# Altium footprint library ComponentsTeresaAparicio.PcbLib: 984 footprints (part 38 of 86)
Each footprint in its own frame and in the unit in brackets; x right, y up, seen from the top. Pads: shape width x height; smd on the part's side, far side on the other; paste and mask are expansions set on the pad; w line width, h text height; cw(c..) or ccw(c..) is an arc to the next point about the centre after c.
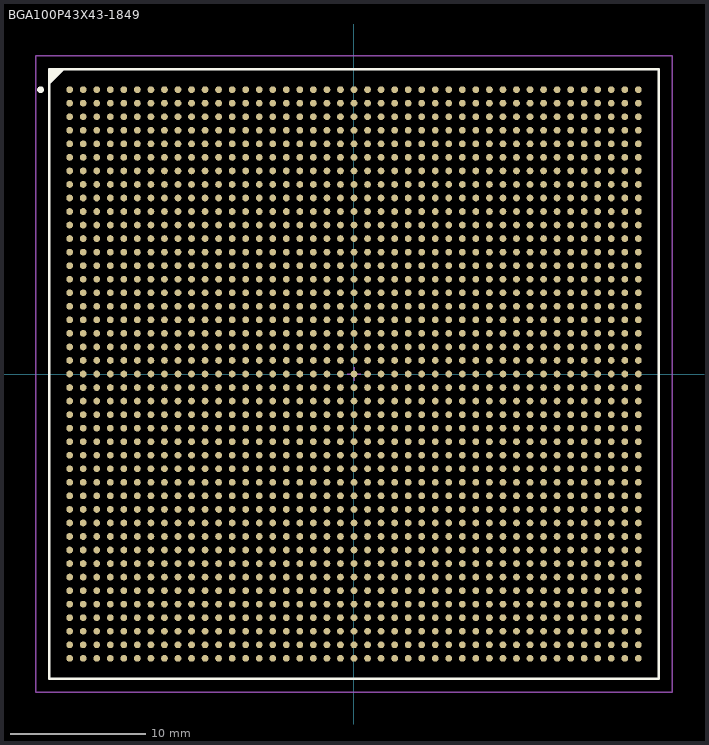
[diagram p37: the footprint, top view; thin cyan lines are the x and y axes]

## BGA100P43X43-1849 [mm] "BGA, 1849-Leads, Body 45x45mm, Pitch 1mm"
height 3.5
pads (1849):
  round 0.5 smd: A1(-21,21) A2(-20,21) A3(-19,21) A4(-18,21) A5(-17,21) A6(-16,21) A7(-15,21) A8(-14,21) A9(-13,21) A10(-12,21) A11(-11,21) A12(-10,21) A13(-9,21) A14(-8,21) A15(-7,21) A16(-6,21) A17(-5,21) A18(-4,21) A19(-3,21) A20(-2,21) A21(-1,21) A22(0,21) A23(1,21) A24(2,21) A25(3,21) A26(4,21) A27(5,21) A28(6,21) A29(7,21) A30(8,21) A31(9,21) A32(10,21) A33(11,21) A34(12,21) A35(13,21) A36(14,21) A37(15,21) A38(16,21) A39(17,21) A40(18,21) A41(19,21) A42(20,21) A43(21,21) AA1(-21,1) AA2(-20,1) AA3(-19,1) AA4(-18,1) AA5(-17,1) AA6(-16,1) AA7(-15,1) AA8(-14,1) AA9(-13,1) AA10(-12,1) AA11(-11,1) AA12(-10,1) AA13(-9,1) AA14(-8,1) AA15(-7,1) AA16(-6,1) AA17(-5,1) AA18(-4,1) AA19(-3,1) AA20(-2,1) AA21(-1,1) AA22(0,1) AA23(1,1) AA24(2,1) AA25(3,1) AA26(4,1) AA27(5,1) AA28(6,1) AA29(7,1) AA30(8,1) AA31(9,1) AA32(10,1) AA33(11,1) AA34(12,1) AA35(13,1) AA36(14,1) AA37(15,1) AA38(16,1) AA39(17,1) AA40(18,1) AA41(19,1) AA42(20,1) AA43(21,1) AB1(-21,0) AB2(-20,0) AB3(-19,0) AB4(-18,0) AB5(-17,0) AB6(-16,0) AB7(-15,0) AB8(-14,0) AB9(-13,0) AB10(-12,0) AB11(-11,0) AB12(-10,0) AB13(-9,0) AB14(-8,0) AB15(-7,0) AB16(-6,0) AB17(-5,0) AB18(-4,0) AB19(-3,0) AB20(-2,0) AB21(-1,0) AB22(0,0) AB23(1,0) AB24(2,0) AB25(3,0) AB26(4,0) AB27(5,0) AB28(6,0) AB29(7,0) AB30(8,0) AB31(9,0) AB32(10,0) AB33(11,0) AB34(12,0) AB35(13,0) AB36(14,0) AB37(15,0) AB38(16,0) AB39(17,0) AB40(18,0) AB41(19,0) AB42(20,0) AB43(21,0) AC1(-21,-1) AC2(-20,-1) AC3(-19,-1) AC4(-18,-1) AC5(-17,-1) AC6(-16,-1) AC7(-15,-1) AC8(-14,-1) AC9(-13,-1) AC10(-12,-1) AC11(-11,-1) AC12(-10,-1) AC13(-9,-1) AC14(-8,-1) AC15(-7,-1) AC16(-6,-1) AC17(-5,-1) AC18(-4,-1) AC19(-3,-1) AC20(-2,-1) AC21(-1,-1) AC22(0,-1) AC23(1,-1) AC24(2,-1) AC25(3,-1) AC26(4,-1) AC27(5,-1) AC28(6,-1) AC29(7,-1) AC30(8,-1) AC31(9,-1) AC32(10,-1) AC33(11,-1) AC34(12,-1) AC35(13,-1) AC36(14,-1) AC37(15,-1) AC38(16,-1) AC39(17,-1) AC40(18,-1) AC41(19,-1) AC42(20,-1) AC43(21,-1) AD1(-21,-2) AD2(-20,-2) AD3(-19,-2) AD4(-18,-2) AD5(-17,-2) AD6(-16,-2) AD7(-15,-2) AD8(-14,-2) AD9(-13,-2) AD10(-12,-2) AD11(-11,-2) AD12(-10,-2) AD13(-9,-2) AD14(-8,-2) AD15(-7,-2) AD16(-6,-2) AD17(-5,-2) AD18(-4,-2) AD19(-3,-2) AD20(-2,-2) AD21(-1,-2) AD22(0,-2) AD23(1,-2) AD24(2,-2) AD25(3,-2) AD26(4,-2) AD27(5,-2) AD28(6,-2) AD29(7,-2) AD30(8,-2) AD31(9,-2) AD32(10,-2) AD33(11,-2) AD34(12,-2) AD35(13,-2) AD36(14,-2) AD37(15,-2) AD38(16,-2) AD39(17,-2) AD40(18,-2) AD41(19,-2) AD42(20,-2) AD43(21,-2) AE1(-21,-3) AE2(-20,-3) AE3(-19,-3) AE4(-18,-3) AE5(-17,-3) AE6(-16,-3) AE7(-15,-3) AE8(-14,-3) AE9(-13,-3) AE10(-12,-3) AE11(-11,-3) AE12(-10,-3) AE13(-9,-3) AE14(-8,-3) AE15(-7,-3) AE16(-6,-3) AE17(-5,-3) AE18(-4,-3) AE19(-3,-3) AE20(-2,-3) AE21(-1,-3) AE22(0,-3) AE23(1,-3) AE24(2,-3) AE25(3,-3) AE26(4,-3) AE27(5,-3) AE28(6,-3) AE29(7,-3) AE30(8,-3) AE31(9,-3) AE32(10,-3) AE33(11,-3) AE34(12,-3) AE35(13,-3) AE36(14,-3) AE37(15,-3) AE38(16,-3) AE39(17,-3) AE40(18,-3) AE41(19,-3) AE42(20,-3) AE43(21,-3) AF1(-21,-4) AF2(-20,-4) AF3(-19,-4) AF4(-18,-4) AF5(-17,-4) AF6(-16,-4) AF7(-15,-4) AF8(-14,-4) AF9(-13,-4) AF10(-12,-4) AF11(-11,-4) AF12(-10,-4) AF13(-9,-4) AF14(-8,-4) AF15(-7,-4) AF16(-6,-4) AF17(-5,-4) AF18(-4,-4) AF19(-3,-4) AF20(-2,-4) AF21(-1,-4) AF22(0,-4) AF23(1,-4) AF24(2,-4) AF25(3,-4) AF26(4,-4) AF27(5,-4) AF28(6,-4) AF29(7,-4) AF30(8,-4) AF31(9,-4) AF32(10,-4) AF33(11,-4) AF34(12,-4) AF35(13,-4) AF36(14,-4) AF37(15,-4) AF38(16,-4) AF39(17,-4) AF40(18,-4) AF41(19,-4) AF42(20,-4) AF43(21,-4) AG1(-21,-5) AG2(-20,-5) AG3(-19,-5) AG4(-18,-5) AG5(-17,-5) AG6(-16,-5) AG7(-15,-5) AG8(-14,-5) AG9(-13,-5) AG10(-12,-5) AG11(-11,-5) AG12(-10,-5) AG13(-9,-5) AG14(-8,-5) AG15(-7,-5) AG16(-6,-5) AG17(-5,-5) AG18(-4,-5) AG19(-3,-5) AG20(-2,-5) AG21(-1,-5) AG22(0,-5) AG23(1,-5) AG24(2,-5) AG25(3,-5) AG26(4,-5) AG27(5,-5) AG28(6,-5) AG29(7,-5) AG30(8,-5) AG31(9,-5) AG32(10,-5) AG33(11,-5) AG34(12,-5) AG35(13,-5) AG36(14,-5) AG37(15,-5) AG38(16,-5) AG39(17,-5) AG40(18,-5) AG41(19,-5) AG42(20,-5) AG43(21,-5) AH1(-21,-6) AH2(-20,-6) AH3(-19,-6) AH4(-18,-6) AH5(-17,-6) AH6(-16,-6) AH7(-15,-6) AH8(-14,-6) AH9(-13,-6) AH10(-12,-6) AH11(-11,-6) AH12(-10,-6) AH13(-9,-6) AH14(-8,-6) AH15(-7,-6) AH16(-6,-6) AH17(-5,-6) AH18(-4,-6) AH19(-3,-6) AH20(-2,-6) AH21(-1,-6) AH22(0,-6) AH23(1,-6) AH24(2,-6) AH25(3,-6) AH26(4,-6) AH27(5,-6) AH28(6,-6) AH29(7,-6) AH30(8,-6) AH31(9,-6) AH32(10,-6) AH33(11,-6) AH34(12,-6) AH35(13,-6) AH36(14,-6) AH37(15,-6) AH38(16,-6) AH39(17,-6) AH40(18,-6) AH41(19,-6) AH42(20,-6) AH43(21,-6) AJ1(-21,-7) AJ2(-20,-7) AJ3(-19,-7) AJ4(-18,-7) AJ5(-17,-7) AJ6(-16,-7) AJ7(-15,-7) AJ8(-14,-7) AJ9(-13,-7) AJ10(-12,-7) AJ11(-11,-7) AJ12(-10,-7) AJ13(-9,-7) AJ14(-8,-7) AJ15(-7,-7) AJ16(-6,-7) AJ17(-5,-7) AJ18(-4,-7) AJ19(-3,-7) AJ20(-2,-7) AJ21(-1,-7) AJ22(0,-7) AJ23(1,-7) AJ24(2,-7) AJ25(3,-7) AJ26(4,-7) AJ27(5,-7) AJ28(6,-7) AJ29(7,-7) AJ30(8,-7) AJ31(9,-7) AJ32(10,-7) AJ33(11,-7) AJ34(12,-7) AJ35(13,-7) AJ36(14,-7) AJ37(15,-7) AJ38(16,-7) AJ39(17,-7) AJ40(18,-7) AJ41(19,-7) AJ42(20,-7) AJ43(21,-7) AK1(-21,-8) AK2(-20,-8) AK3(-19,-8) AK4(-18,-8) AK5(-17,-8) AK6(-16,-8) AK7(-15,-8) AK8(-14,-8) AK9(-13,-8) AK10(-12,-8) AK11(-11,-8) AK12(-10,-8) AK13(-9,-8) AK14(-8,-8) AK15(-7,-8) AK16(-6,-8) AK17(-5,-8) AK18(-4,-8) AK19(-3,-8) AK20(-2,-8) AK21(-1,-8) AK22(0,-8) AK23(1,-8) AK24(2,-8) AK25(3,-8) AK26(4,-8) AK27(5,-8) AK28(6,-8) AK29(7,-8) AK30(8,-8) AK31(9,-8) AK32(10,-8) AK33(11,-8) AK34(12,-8) AK35(13,-8) AK36(14,-8) AK37(15,-8) AK38(16,-8) AK39(17,-8) AK40(18,-8) AK41(19,-8) AK42(20,-8) AK43(21,-8) AL1(-21,-9) AL2(-20,-9) AL3(-19,-9) AL4(-18,-9) AL5(-17,-9) AL6(-16,-9) AL7(-15,-9) AL8(-14,-9) AL9(-13,-9) AL10(-12,-9) AL11(-11,-9) AL12(-10,-9) AL13(-9,-9) AL14(-8,-9) AL15(-7,-9) AL16(-6,-9) AL17(-5,-9) AL18(-4,-9) AL19(-3,-9) AL20(-2,-9) AL21(-1,-9) AL22(0,-9) AL23(1,-9) AL24(2,-9) AL25(3,-9) AL26(4,-9) AL27(5,-9) AL28(6,-9) AL29(7,-9) AL30(8,-9) AL31(9,-9) AL32(10,-9) AL33(11,-9) AL34(12,-9) AL35(13,-9) AL36(14,-9) AL37(15,-9) AL38(16,-9) AL39(17,-9) AL40(18,-9) AL41(19,-9) AL42(20,-9) AL43(21,-9) AM1(-21,-10) AM2(-20,-10) AM3(-19,-10) AM4(-18,-10) AM5(-17,-10) AM6(-16,-10) AM7(-15,-10) AM8(-14,-10) AM9(-13,-10) AM10(-12,-10) AM11(-11,-10) AM12(-10,-10) AM13(-9,-10) AM14(-8,-10) AM15(-7,-10) AM16(-6,-10) AM17(-5,-10) AM18(-4,-10) AM19(-3,-10) AM20(-2,-10) AM21(-1,-10) AM22(0,-10) AM23(1,-10) AM24(2,-10) AM25(3,-10) AM26(4,-10) AM27(5,-10) AM28(6,-10) AM29(7,-10) AM30(8,-10) AM31(9,-10) AM32(10,-10) AM33(11,-10) AM34(12,-10) AM35(13,-10) AM36(14,-10) AM37(15,-10) AM38(16,-10) AM39(17,-10) AM40(18,-10) AM41(19,-10) AM42(20,-10) AM43(21,-10) AN1(-21,-11) AN2(-20,-11) AN3(-19,-11) AN4(-18,-11) AN5(-17,-11) AN6(-16,-11) AN7(-15,-11) AN8(-14,-11) AN9(-13,-11) AN10(-12,-11) AN11(-11,-11) AN12(-10,-11) AN13(-9,-11) AN14(-8,-11) AN15(-7,-11) AN16(-6,-11) AN17(-5,-11) AN18(-4,-11) AN19(-3,-11) AN20(-2,-11) AN21(-1,-11) AN22(0,-11) AN23(1,-11) AN24(2,-11) AN25(3,-11) AN26(4,-11) AN27(5,-11) AN28(6,-11) AN29(7,-11) AN30(8,-11) AN31(9,-11) AN32(10,-11) AN33(11,-11) AN34(12,-11) AN35(13,-11) AN36(14,-11) AN37(15,-11) AN38(16,-11) AN39(17,-11) AN40(18,-11) AN41(19,-11) AN42(20,-11) AN43(21,-11) AP1(-21,-12) AP2(-20,-12) AP3(-19,-12) AP4(-18,-12) AP5(-17,-12) AP6(-16,-12) AP7(-15,-12) AP8(-14,-12) AP9(-13,-12) AP10(-12,-12) AP11(-11,-12) AP12(-10,-12) AP13(-9,-12) AP14(-8,-12) AP15(-7,-12) AP16(-6,-12) AP17(-5,-12) AP18(-4,-12) AP19(-3,-12) AP20(-2,-12) AP21(-1,-12) AP22(0,-12) AP23(1,-12) AP24(2,-12) AP25(3,-12) AP26(4,-12) AP27(5,-12) AP28(6,-12) AP29(7,-12) AP30(8,-12) AP31(9,-12) AP32(10,-12) AP33(11,-12) AP34(12,-12) AP35(13,-12) AP36(14,-12) AP37(15,-12) AP38(16,-12) AP39(17,-12) AP40(18,-12) AP41(19,-12) AP42(20,-12) AP43(21,-12) AR1(-21,-13) AR2(-20,-13) AR3(-19,-13) AR4(-18,-13) AR5(-17,-13) AR6(-16,-13) AR7(-15,-13) AR8(-14,-13) AR9(-13,-13) AR10(-12,-13) AR11(-11,-13) AR12(-10,-13) AR13(-9,-13) AR14(-8,-13) AR15(-7,-13) AR16(-6,-13) AR17(-5,-13) AR18(-4,-13) AR19(-3,-13) AR20(-2,-13) AR21(-1,-13) AR22(0,-13) AR23(1,-13) AR24(2,-13) AR25(3,-13) AR26(4,-13) AR27(5,-13) AR28(6,-13) AR29(7,-13) AR30(8,-13) AR31(9,-13) AR32(10,-13) AR33(11,-13) AR34(12,-13) AR35(13,-13) AR36(14,-13) AR37(15,-13) AR38(16,-13) AR39(17,-13) AR40(18,-13) AR41(19,-13) AR42(20,-13) AR43(21,-13) AT1(-21,-14) AT2(-20,-14) AT3(-19,-14) AT4(-18,-14) AT5(-17,-14) AT6(-16,-14) AT7(-15,-14) AT8(-14,-14) AT9(-13,-14) AT10(-12,-14) AT11(-11,-14) AT12(-10,-14) AT13(-9,-14) AT14(-8,-14) AT15(-7,-14) AT16(-6,-14) AT17(-5,-14) AT18(-4,-14) AT19(-3,-14) AT20(-2,-14) AT21(-1,-14) AT22(0,-14) AT23(1,-14) AT24(2,-14) AT25(3,-14) AT26(4,-14) AT27(5,-14) AT28(6,-14) AT29(7,-14) AT30(8,-14) AT31(9,-14) AT32(10,-14) AT33(11,-14) AT34(12,-14) AT35(13,-14) AT36(14,-14) AT37(15,-14) AT38(16,-14) AT39(17,-14) AT40(18,-14) AT41(19,-14) AT42(20,-14) AT43(21,-14) AU1(-21,-15) AU2(-20,-15) AU3(-19,-15) AU4(-18,-15) AU5(-17,-15) AU6(-16,-15) AU7(-15,-15) AU8(-14,-15) AU9(-13,-15) AU10(-12,-15) AU11(-11,-15) AU12(-10,-15) AU13(-9,-15) AU14(-8,-15) AU15(-7,-15) AU16(-6,-15) AU17(-5,-15) AU18(-4,-15) AU19(-3,-15) AU20(-2,-15) AU21(-1,-15) AU22(0,-15) AU23(1,-15) AU24(2,-15) AU25(3,-15) AU26(4,-15) AU27(5,-15) AU28(6,-15) AU29(7,-15) AU30(8,-15) AU31(9,-15) AU32(10,-15) AU33(11,-15) AU34(12,-15) AU35(13,-15) AU36(14,-15) AU37(15,-15) AU38(16,-15) AU39(17,-15) AU40(18,-15) AU41(19,-15) AU42(20,-15) AU43(21,-15) AV1(-21,-16) AV2(-20,-16) AV3(-19,-16) AV4(-18,-16) AV5(-17,-16) AV6(-16,-16) AV7(-15,-16) AV8(-14,-16) AV9(-13,-16) AV10(-12,-16) AV11(-11,-16) AV12(-10,-16) AV13(-9,-16) AV14(-8,-16) AV15(-7,-16) AV16(-6,-16) AV17(-5,-16) AV18(-4,-16) AV19(-3,-16) AV20(-2,-16) AV21(-1,-16) AV22(0,-16) AV23(1,-16) AV24(2,-16) AV25(3,-16) AV26(4,-16) AV27(5,-16) AV28(6,-16) AV29(7,-16) AV30(8,-16) AV31(9,-16) AV32(10,-16) AV33(11,-16) AV34(12,-16) AV35(13,-16) AV36(14,-16) AV37(15,-16) AV38(16,-16) AV39(17,-16) AV40(18,-16) AV41(19,-16) AV42(20,-16) AV43(21,-16) AW1(-21,-17) AW2(-20,-17) AW3(-19,-17) AW4(-18,-17) AW5(-17,-17) AW6(-16,-17) AW7(-15,-17) AW8(-14,-17) AW9(-13,-17) AW10(-12,-17) AW11(-11,-17) AW12(-10,-17) AW13(-9,-17) AW14(-8,-17) AW15(-7,-17) AW16(-6,-17) AW17(-5,-17) AW18(-4,-17) AW19(-3,-17) AW20(-2,-17) AW21(-1,-17) AW22(0,-17) AW23(1,-17) AW24(2,-17) AW25(3,-17) AW26(4,-17) AW27(5,-17) AW28(6,-17) AW29(7,-17) AW30(8,-17) AW31(9,-17) AW32(10,-17) AW33(11,-17) AW34(12,-17) AW35(13,-17) AW36(14,-17) AW37(15,-17) AW38(16,-17) AW39(17,-17) AW40(18,-17) AW41(19,-17) AW42(20,-17) AW43(21,-17) AY1(-21,-18) AY2(-20,-18) AY3(-19,-18) AY4(-18,-18) AY5(-17,-18) AY6(-16,-18) AY7(-15,-18) AY8(-14,-18) AY9(-13,-18) AY10(-12,-18) AY11(-11,-18) AY12(-10,-18) AY13(-9,-18) AY14(-8,-18) AY15(-7,-18) AY16(-6,-18) AY17(-5,-18) AY18(-4,-18) AY19(-3,-18) AY20(-2,-18) AY21(-1,-18) AY22(0,-18) AY23(1,-18) AY24(2,-18) AY25(3,-18) AY26(4,-18) AY27(5,-18) AY28(6,-18) AY29(7,-18) AY30(8,-18) AY31(9,-18) AY32(10,-18) AY33(11,-18) AY34(12,-18) AY35(13,-18) AY36(14,-18) AY37(15,-18) AY38(16,-18) AY39(17,-18) AY40(18,-18) AY41(19,-18) AY42(20,-18) AY43(21,-18) B1(-21,20) B2(-20,20) B3(-19,20) B4(-18,20) B5(-17,20) B6(-16,20) B7(-15,20) B8(-14,20) B9(-13,20) B10(-12,20) B11(-11,20) B12(-10,20) B13(-9,20) B14(-8,20) B15(-7,20) B16(-6,20) B17(-5,20) B18(-4,20) B19(-3,20) B20(-2,20) B21(-1,20) B22(0,20) B23(1,20) B24(2,20) B25(3,20) B26(4,20) B27(5,20) B28(6,20) B29(7,20) B30(8,20) B31(9,20) B32(10,20) B33(11,20) B34(12,20) B35(13,20) B36(14,20) B37(15,20) B38(16,20) B39(17,20) B40(18,20) B41(19,20) B42(20,20) B43(21,20) BA1(-21,-19) BA2(-20,-19) BA3(-19,-19) BA4(-18,-19) BA5(-17,-19) BA6(-16,-19) BA7(-15,-19) BA8(-14,-19) BA9(-13,-19) BA10(-12,-19) BA11(-11,-19) BA12(-10,-19) BA13(-9,-19) BA14(-8,-19) BA15(-7,-19) BA16(-6,-19) BA17(-5,-19) BA18(-4,-19) BA19(-3,-19) BA20(-2,-19) BA21(-1,-19) BA22(0,-19) BA23(1,-19) BA24(2,-19) BA25(3,-19) BA26(4,-19) BA27(5,-19) BA28(6,-19) BA29(7,-19) BA30(8,-19) BA31(9,-19) BA32(10,-19) BA33(11,-19) BA34(12,-19) BA35(13,-19) BA36(14,-19) BA37(15,-19) BA38(16,-19) BA39(17,-19) BA40(18,-19) BA41(19,-19) BA42(20,-19) BA43(21,-19) BB1(-21,-20) BB2(-20,-20) BB3(-19,-20) BB4(-18,-20) BB5(-17,-20) BB6(-16,-20) BB7(-15,-20) BB8(-14,-20) BB9(-13,-20) BB10(-12,-20) BB11(-11,-20) BB12(-10,-20) BB13(-9,-20) BB14(-8,-20) BB15(-7,-20) BB16(-6,-20) BB17(-5,-20) BB18(-4,-20) BB19(-3,-20) BB20(-2,-20) BB21(-1,-20) BB22(0,-20) BB23(1,-20) BB24(2,-20) BB25(3,-20) BB26(4,-20) BB27(5,-20) BB28(6,-20) BB29(7,-20) BB30(8,-20) BB31(9,-20) BB32(10,-20) BB33(11,-20) BB34(12,-20) BB35(13,-20) BB36(14,-20) BB37(15,-20) BB38(16,-20) BB39(17,-20) BB40(18,-20) BB41(19,-20) BB42(20,-20) BB43(21,-20) BC1(-21,-21) BC2(-20,-21) BC3(-19,-21) BC4(-18,-21) BC5(-17,-21) BC6(-16,-21) BC7(-15,-21) BC8(-14,-21) BC9(-13,-21) BC10(-12,-21) BC11(-11,-21) BC12(-10,-21) BC13(-9,-21) BC14(-8,-21) BC15(-7,-21) BC16(-6,-21) BC17(-5,-21) BC18(-4,-21) BC19(-3,-21) BC20(-2,-21) BC21(-1,-21) BC22(0,-21) BC23(1,-21) BC24(2,-21) BC25(3,-21) BC26(4,-21) BC27(5,-21) BC28(6,-21) BC29(7,-21) BC30(8,-21) BC31(9,-21) BC32(10,-21) BC33(11,-21) BC34(12,-21) BC35(13,-21) BC36(14,-21) BC37(15,-21) BC38(16,-21) BC39(17,-21) BC40(18,-21) BC41(19,-21) BC42(20,-21) BC43(21,-21) C1(-21,19) C2(-20,19) C3(-19,19) C4(-18,19) C5(-17,19) C6(-16,19) C7(-15,19) C8(-14,19) C9(-13,19) C10(-12,19) C11(-11,19) C12(-10,19) C13(-9,19) C14(-8,19) C15(-7,19) C16(-6,19) C17(-5,19) C18(-4,19) C19(-3,19) C20(-2,19) C21(-1,19) C22(0,19) C23(1,19) C24(2,19) C25(3,19) C26(4,19) C27(5,19) C28(6,19) C29(7,19) C30(8,19) C31(9,19) C32(10,19) C33(11,19) C34(12,19) C35(13,19) C36(14,19) C37(15,19) C38(16,19) C39(17,19) C40(18,19) C41(19,19) C42(20,19) C43(21,19) D1(-21,18) D2(-20,18) D3(-19,18) D4(-18,18) D5(-17,18) D6(-16,18) D7(-15,18) D8(-14,18) D9(-13,18) D10(-12,18) D11(-11,18) D12(-10,18) D13(-9,18) D14(-8,18) D15(-7,18) D16(-6,18) D17(-5,18) D18(-4,18) D19(-3,18) D20(-2,18) D21(-1,18) D22(0,18) D23(1,18) D24(2,18) D25(3,18) D26(4,18) D27(5,18) D28(6,18) D29(7,18) D30(8,18) D31(9,18) D32(10,18) D33(11,18) D34(12,18) D35(13,18) D36(14,18) D37(15,18) D38(16,18) D39(17,18) D40(18,18) D41(19,18) D42(20,18) D43(21,18) E1(-21,17) E2(-20,17) E3(-19,17) E4(-18,17) E5(-17,17) E6(-16,17) E7(-15,17) E8(-14,17) E9(-13,17) E10(-12,17) E11(-11,17) E12(-10,17) E13(-9,17) E14(-8,17) E15(-7,17) E16(-6,17) E17(-5,17) E18(-4,17) E19(-3,17) E20(-2,17) E21(-1,17) E22(0,17) E23(1,17) E24(2,17) E25(3,17) E26(4,17) E27(5,17) E28(6,17) E29(7,17) E30(8,17) E31(9,17) E32(10,17) E33(11,17) E34(12,17) E35(13,17) E36(14,17) E37(15,17) E38(16,17) E39(17,17) E40(18,17) E41(19,17) E42(20,17) E43(21,17) F1(-21,16) F2(-20,16) F3(-19,16) F4(-18,16) F5(-17,16) F6(-16,16) F7(-15,16) F8(-14,16) F9(-13,16) F10(-12,16) F11(-11,16) F12(-10,16) F13(-9,16) F14(-8,16) F15(-7,16) F16(-6,16) F17(-5,16) F18(-4,16) F19(-3,16) F20(-2,16) F21(-1,16) F22(0,16) F23(1,16) F24(2,16) F25(3,16) F26(4,16) F27(5,16) F28(6,16) F29(7,16) F30(8,16) F31(9,16) F32(10,16) F33(11,16) F34(12,16) F35(13,16) F36(14,16) F37(15,16) F38(16,16) F39(17,16) F40(18,16) F41(19,16) F42(20,16) F43(21,16) G1(-21,15) G2(-20,15) G3(-19,15) G4(-18,15) G5(-17,15) G6(-16,15) G7(-15,15) G8(-14,15) G9(-13,15) G10(-12,15) G11(-11,15) G12(-10,15) G13(-9,15) G14(-8,15) G15(-7,15) G16(-6,15) G17(-5,15) G18(-4,15) G19(-3,15) G20(-2,15) G21(-1,15) G22(0,15) G23(1,15) G24(2,15) G25(3,15) G26(4,15) G27(5,15) G28(6,15) G29(7,15) G30(8,15) G31(9,15) G32(10,15) G33(11,15) G34(12,15) G35(13,15) G36(14,15) G37(15,15) G38(16,15) G39(17,15) G40(18,15) G41(19,15) G42(20,15) G43(21,15) H1(-21,14) H2(-20,14) H3(-19,14) H4(-18,14) H5(-17,14) H6(-16,14) H7(-15,14) H8(-14,14) H9(-13,14) H10(-12,14) H11(-11,14) H12(-10,14) H13(-9,14) H14(-8,14) H15(-7,14) H16(-6,14) H17(-5,14) H18(-4,14) H19(-3,14) H20(-2,14) H21(-1,14) H22(0,14) H23(1,14) H24(2,14) H25(3,14) H26(4,14) H27(5,14) H28(6,14) H29(7,14) H30(8,14) H31(9,14) H32(10,14) H33(11,14) H34(12,14) H35(13,14) H36(14,14) H37(15,14) H38(16,14) H39(17,14) H40(18,14) H41(19,14) H42(20,14) H43(21,14) J1(-21,13) J2(-20,13) J3(-19,13) J4(-18,13) J5(-17,13) J6(-16,13) J7(-15,13) J8(-14,13) J9(-13,13) J10(-12,13) J11(-11,13) J12(-10,13) J13(-9,13) J14(-8,13) J15(-7,13) J16(-6,13) J17(-5,13) J18(-4,13) J19(-3,13) J20(-2,13) J21(-1,13) J22(0,13) J23(1,13) J24(2,13) J25(3,13) J26(4,13) J27(5,13) J28(6,13) J29(7,13) J30(8,13) J31(9,13) J32(10,13) J33(11,13) J34(12,13) J35(13,13) J36(14,13) J37(15,13) J38(16,13) J39(17,13) J40(18,13) J41(19,13) J42(20,13) J43(21,13) K1(-21,12) K2(-20,12) K3(-19,12) K4(-18,12) K5(-17,12) K6(-16,12) K7(-15,12) K8(-14,12) K9(-13,12) K10(-12,12) K11(-11,12) K12(-10,12) K13(-9,12) K14(-8,12) K15(-7,12) K16(-6,12) K17(-5,12) K18(-4,12) K19(-3,12) K20(-2,12) K21(-1,12) K22(0,12) K23(1,12) K24(2,12) K25(3,12) K26(4,12) K27(5,12) K28(6,12) K29(7,12) K30(8,12) K31(9,12) K32(10,12) K33(11,12) K34(12,12) K35(13,12) K36(14,12) K37(15,12) K38(16,12) K39(17,12) K40(18,12) K41(19,12) K42(20,12) K43(21,12) L1(-21,11) L2(-20,11) L3(-19,11) L4(-18,11) L5(-17,11) L6(-16,11) L7(-15,11) L8(-14,11) L9(-13,11) L10(-12,11) L11(-11,11) L12(-10,11) L13(-9,11) L14(-8,11) L15(-7,11) L16(-6,11) L17(-5,11) L18(-4,11) L19(-3,11) L20(-2,11) L21(-1,11) L22(0,11) L23(1,11) L24(2,11) L25(3,11) L26(4,11) L27(5,11) L28(6,11) L29(7,11) L30(8,11) L31(9,11) L32(10,11) L33(11,11) L34(12,11) L35(13,11) L36(14,11) L37(15,11) L38(16,11) L39(17,11) L40(18,11) L41(19,11) L42(20,11) L43(21,11) M1(-21,10) M2(-20,10) M3(-19,10) M4(-18,10) M5(-17,10) M6(-16,10) M7(-15,10) M8(-14,10) M9(-13,10) M10(-12,10) M11(-11,10) M12(-10,10) M13(-9,10) M14(-8,10) M15(-7,10) M16(-6,10) M17(-5,10) M18(-4,10) M19(-3,10) M20(-2,10) M21(-1,10) M22(0,10) M23(1,10) M24(2,10) M25(3,10) M26(4,10) M27(5,10) M28(6,10) M29(7,10) M30(8,10) M31(9,10) M32(10,10) M33(11,10) M34(12,10) M35(13,10) M36(14,10) M37(15,10) M38(16,10) M39(17,10) M40(18,10) M41(19,10) M42(20,10) M43(21,10) N1(-21,9) N2(-20,9) N3(-19,9) N4(-18,9) N5(-17,9) N6(-16,9) N7(-15,9) N8(-14,9) N9(-13,9) N10(-12,9) N11(-11,9) N12(-10,9) N13(-9,9) N14(-8,9) N15(-7,9) N16(-6,9) N17(-5,9) N18(-4,9) N19(-3,9) N20(-2,9) N21(-1,9) N22(0,9) N23(1,9) N24(2,9) N25(3,9) N26(4,9) N27(5,9) N28(6,9) N29(7,9) N30(8,9) N31(9,9) N32(10,9) N33(11,9) N34(12,9) N35(13,9) N36(14,9) N37(15,9) N38(16,9) N39(17,9) N40(18,9) N41(19,9) N42(20,9) N43(21,9) P1(-21,8) P2(-20,8) P3(-19,8) P4(-18,8) P5(-17,8) P6(-16,8) P7(-15,8) P8(-14,8) P9(-13,8) P10(-12,8) P11(-11,8) P12(-10,8) P13(-9,8) P14(-8,8) P15(-7,8) P16(-6,8) P17(-5,8) P18(-4,8) P19(-3,8) P20(-2,8) P21(-1,8) P22(0,8) P23(1,8) P24(2,8) P25(3,8) P26(4,8) P27(5,8) P28(6,8) P29(7,8) P30(8,8) P31(9,8) P32(10,8) P33(11,8) P34(12,8) P35(13,8) P36(14,8) P37(15,8) P38(16,8) P39(17,8) P40(18,8) P41(19,8) P42(20,8) P43(21,8) R1(-21,7) R2(-20,7) R3(-19,7) R4(-18,7) R5(-17,7) R6(-16,7) R7(-15,7) R8(-14,7) R9(-13,7) R10(-12,7) R11(-11,7) R12(-10,7) R13(-9,7) R14(-8,7) R15(-7,7) R16(-6,7) R17(-5,7) R18(-4,7) R19(-3,7) R20(-2,7) R21(-1,7) R22(0,7) R23(1,7) R24(2,7) R25(3,7) R26(4,7) R27(5,7) R28(6,7) R29(7,7) R30(8,7) R31(9,7) R32(10,7) R33(11,7) R34(12,7) R35(13,7) R36(14,7) R37(15,7) R38(16,7) R39(17,7) R40(18,7) R41(19,7) R42(20,7) R43(21,7) T1(-21,6) T2(-20,6) T3(-19,6) T4(-18,6) T5(-17,6) T6(-16,6) T7(-15,6) T8(-14,6) T9(-13,6) T10(-12,6) T11(-11,6) T12(-10,6) T13(-9,6) T14(-8,6) T15(-7,6) T16(-6,6) T17(-5,6) T18(-4,6) T19(-3,6) T20(-2,6) T21(-1,6) T22(0,6) T23(1,6) T24(2,6) T25(3,6) T26(4,6) T27(5,6) T28(6,6) T29(7,6) T30(8,6) T31(9,6) T32(10,6) T33(11,6) T34(12,6) T35(13,6) T36(14,6) T37(15,6) T38(16,6) T39(17,6) T40(18,6) T41(19,6) T42(20,6) T43(21,6) U1(-21,5) U2(-20,5) U3(-19,5) U4(-18,5) U5(-17,5) U6(-16,5) U7(-15,5) U8(-14,5) U9(-13,5) U10(-12,5) U11(-11,5) U12(-10,5) U13(-9,5) U14(-8,5) U15(-7,5) U16(-6,5) U17(-5,5) U18(-4,5) U19(-3,5) U20(-2,5) U21(-1,5) U22(0,5) U23(1,5) U24(2,5) U25(3,5) U26(4,5) U27(5,5) U28(6,5) U29(7,5) U30(8,5) U31(9,5) U32(10,5) U33(11,5) U34(12,5) U35(13,5) U36(14,5) U37(15,5) U38(16,5) U39(17,5) U40(18,5) U41(19,5) U42(20,5) U43(21,5) V1(-21,4) V2(-20,4) V3(-19,4) V4(-18,4) V5(-17,4) V6(-16,4) V7(-15,4) V8(-14,4) V9(-13,4) V10(-12,4) V11(-11,4) V12(-10,4) V13(-9,4) V14(-8,4) V15(-7,4) V16(-6,4) V17(-5,4) V18(-4,4) V19(-3,4) V20(-2,4) V21(-1,4) V22(0,4) V23(1,4) V24(2,4) V25(3,4) V26(4,4) V27(5,4) V28(6,4) V29(7,4) V30(8,4) V31(9,4) V32(10,4) V33(11,4) V34(12,4) V35(13,4) V36(14,4) V37(15,4) V38(16,4) V39(17,4) V40(18,4) V41(19,4) V42(20,4) V43(21,4) W1(-21,3) W2(-20,3) W3(-19,3) W4(-18,3) W5(-17,3) W6(-16,3) W7(-15,3) W8(-14,3) W9(-13,3) W10(-12,3) W11(-11,3) W12(-10,3) W13(-9,3) W14(-8,3) W15(-7,3) W16(-6,3) W17(-5,3) W18(-4,3) W19(-3,3) W20(-2,3) W21(-1,3) W22(0,3) W23(1,3) W24(2,3) W25(3,3) W26(4,3) W27(5,3) W28(6,3) W29(7,3) W30(8,3) W31(9,3) W32(10,3) W33(11,3) W34(12,3) W35(13,3) W36(14,3) W37(15,3) W38(16,3) W39(17,3) W40(18,3) W41(19,3) W42(20,3) W43(21,3) Y1(-21,2) Y2(-20,2) Y3(-19,2) Y4(-18,2) Y5(-17,2) Y6(-16,2) Y7(-15,2) Y8(-14,2) Y9(-13,2) Y10(-12,2) Y11(-11,2) Y12(-10,2) Y13(-9,2) Y14(-8,2) Y15(-7,2) Y16(-6,2) Y17(-5,2) Y18(-4,2) Y19(-3,2) Y20(-2,2) Y21(-1,2) Y22(0,2) Y23(1,2) Y24(2,2) Y25(3,2) Y26(4,2) Y27(5,2) Y28(6,2) Y29(7,2) Y30(8,2) Y31(9,2) Y32(10,2) Y33(11,2) Y34(12,2) Y35(13,2) Y36(14,2) Y37(15,2) Y38(16,2) Y39(17,2) Y40(18,2) Y41(19,2) Y42(20,2) Y43(21,2)
Top Overlay:
  circle w0.25: c-23.15,21 r0.125
  region: -21.5,22.5 -22.5,21.5 -22.5,22.5
  lines w0.2: -22.5,21.5 -21.5,22.5 ; -22.5,-22.5 -22.5,22.5 22.5,22.5 22.5,-22.5 -22.5,-22.5
Mechanical 13:
  lines w0.1: -22.5,-22.5 -22.5,22.5 22.5,22.5 22.5,-22.5 -22.5,-22.5
Mechanical 15:
  lines w0.1: -0.5,0 0.5,0 ; 0,-0.5 0,0.5 ; -23.5,-23.5 -23.5,23.5 23.5,23.5 23.5,-23.5 -23.5,-23.5
3D body: height 0, standoff 0, extent -22.5,-22.5 22.5,22.5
